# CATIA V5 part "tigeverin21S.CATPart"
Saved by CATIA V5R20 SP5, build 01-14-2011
Part number: tigeverin21S
Publications: "Droite.1", "Plan.1"
Bounding box of the stored display mesh (mm): x -250 to 250, y -200 to -200, z 30 to 30
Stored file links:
  U:\think motion\fin\tigeverin21S.CATPart
  U:\think motion\fin\squelette.CATProduct
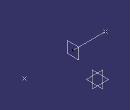
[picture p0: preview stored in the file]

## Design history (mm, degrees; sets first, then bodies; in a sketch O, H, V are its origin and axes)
External parameters (linked from other documents)
  `External.longueur tige verin2` = 200 mm
Set1
  Point1: linked copy from another document
  Point2: linked copy from another document
Set2
  Line1: type PtDir, RefPoint Point1, Direction yz-plane, Start 0, End 200 {= `External.longueur tige verin2`}
  Plane1: type Normal, Curve Line1, RefPoint vertex of Line1
Body1 (main body)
